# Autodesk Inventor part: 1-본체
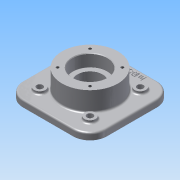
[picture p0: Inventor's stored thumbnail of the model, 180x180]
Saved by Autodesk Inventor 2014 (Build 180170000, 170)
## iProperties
Created: 2015-09
Part Number: 1-본체
Material: 알루미늄 6061
Document SubType Name: Modeling
Designer: study
Density: 2.71 g/cm^3
Appearance: 알루미늄 - 평지
Mass: 1464.66 g
Surface Area: 800.918 cm^2
Volume: 540.466 cm^3
Author: study
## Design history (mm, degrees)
sketch "스케치1"
  geometry: L1 (-45, 75)-(45, 75); L2 (75, 45)-(75, -45); L3 (45, -75)-(-45, -75); L4 (-75, -45)-(-75, 45); L5 (-75, 75)-(75, -75); L6 (75, 75)-(-75, -75); A1 r 30 centre (-45, 45) between (-45, 75) and (-75, 45); A2 r 30 centre (45, 45) between (75, 45) and (45, 75); A3 r 30 centre (45, -45) between (45, -75) and (75, -45); A4 r 30 centre (-45, -45) between (-75, -45) and (-45, -75); 1 further point
  constraints: 12 end point, 8 point on circle, 8 point on line, 8 tangent, 4 centre point, 3 equal radius, 2 midpoint, 2 parallel, 1 horizontal, 1 perpendicular
  dimensions: "d0" = 150 distance of L5.start L6.start; "d1" = 150 distance of L6.start L5.end; "d2" = 30 radius of A1
extrude "돌출1" new body sketch "스케치1" distance "d3" = 12; taper "d4" = 0 deg
node "작업 평면1"
sketch "스케치2"
  geometry: C1 r 50 at (0, 0); 1 further point
  constraints: 1 centre point, 1 coincident
  dimensions: "d6" = 100 diameter of C1
extrude "돌출2" join sketch "스케치2" distance "d7" = 70; taper "d8" = 0 deg
hole "구멍1" diameter "d11" = 45; stored, may be unused: countersink angle "d15" = 90 deg, drill point angle "d17" = 118 deg; dims "d9" = 10, "d10" = 10, "d12" = 6, "d13" = 62, "d14" = 22, "d16" = 8
hole "구멍2" diameter "d20" = 45; stored, may be unused: countersink angle "d24" = 90 deg, drill point angle "d26" = 118 deg; dims "d18" = 10, "d19" = 10, "d21" = 6, "d22" = 62, "d23" = 22, "d25" = 8
sketch "스케치3"
  geometry: C1 r 10 at (-45, 45); C2 r 10 at (45, 45); C3 r 10 at (45, -45); C4 r 10 at (-45, -45); A1 r 30 centre (-45, 45) between (-45, 75) and (-75, 45) reference; A2 r 30 centre (-45, -45) between (-75, -45) and (-45, -75) reference; A3 r 30 centre (45, -45) between (45, -75) and (75, -45) reference; A4 r 30 centre (45, 45) between (75, 45) and (45, 75) reference
  constraints: 4 centre point, 4 coincident, 3 equal radius
  dimensions: "d27" = 20 diameter of C1
extrude "돌출3" join sketch "스케치3" distance "d28" = 5; taper "d29" = 0 deg
sketch "스케치4"
  geometry: C1 r 10 at (0, 0) reference; C2 r 10 at (90, 0) reference; C3 r 10 at (90, -90) reference; C4 r 10 at (0, -90) reference; 5 further points
  constraints: 4 coincident
hole "구멍3" sketch "스케치4" at (0, 0), (90, 0), (90, -90), (0, -90) diameter "d30" = 11; stored, may be unused: countersink angle "d34" = 90 deg, drill point angle "d36" = 118 deg; dims "d31" = 6, "d32" = 62, "d33" = 22, "d35" = 8
sketch "스케치5"
  geometry: L1 (28.991, -28.991)-(-28.991, -28.991); L2 (-28.991, -28.991)-(-28.991, 28.991); L3 (-28.991, 28.991)-(28.991, 28.991); L4 (28.991, 28.991)-(28.991, -28.991); C1 r 50 at (0, 0) reference; 5 further points
  constraints: 8 end point, 5 coincident, 1 horizontal, 9 other
  dimensions: "d37" = 82 distance of L1.start L2.end
hole "구멍4" sketch "스케치5" at (-28.991, 28.991), (28.991, 28.991), (28.991, -28.991), (-28.991, -28.991) diameter "d38" = 4.917; stored, may be unused: countersink angle "d42" = 90 deg, drill point angle "d44" = 118 deg; dims "d39" = 10, "d40" = 62, "d41" = 22, "d43" = 13
node "작업 평면2"
sketch "스케치6"
  geometry: C1 r 50 at (0, 0) reference; 1 further point
  constraints: 1 vertical alignment, 1 other
  dimensions: "d45" = 65 distance of C1.centre point (0, 65)
feature "엠보싱1" sketch "스케치6" dims "d0" = 150, "d1" = 150, "d2" = 30, "d12" = 6, "d46" = 1, "d47" = 0
chamfer "모따기1" distance "d48" = 1; stored, may be unused: second distance "d49" = 2, angle "d50" = 45 deg
fillet "모깎기1" dims "d51" = 0.3, "d52" = 3
node "솔리드1"
mirror "대칭1"
node "투영된 루프1"
node "투영된 루프2"
node "투영된 루프3"
other parameters: "d5" = 23
